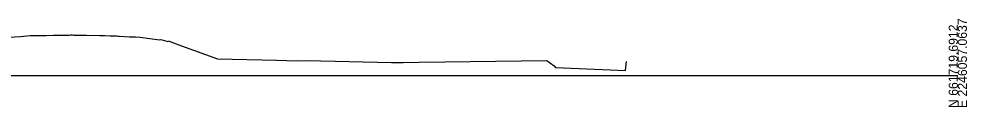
# Model space of a CAD drawing. Extents: x -26 to 603, y -10 to 9526.
# Drawn here: x 311.2 to 602.8, y 990.3 to 1017.3 of the extents above; entities that cross this region are included whole.
import ezdxf

# ---------------------------------------------------------------- set-up
doc = ezdxf.new("R2010")
doc.units = 0
doc.layers.add('Exist Cross Section Cell', color=7, linetype='Continuous')
doc.layers.add('Exist XS Ground Line', color=7, linetype='Continuous')

msp = doc.modelspace()

# ---------------------------------------------------------------- linework, layer by layer
at = {"layer": 'Exist Cross Section Cell'}
msp.add_line((300, 1000), (600, 1000), dxfattribs=at)
at = {"layer": 'Exist XS Ground Line'}
for p, q in [((311.64, 1011.98), (314.69, 1012.19)), ((314.69, 1012.19), (315.53, 1012.27)), ((315.53, 1012.27), (316.19, 1012.24)), ((316.19, 1012.24), (318.76, 1012.26)), ((318.76, 1012.26), (319.58, 1012.27)), ((319.58, 1012.27), (321.78, 1012.3)), ((321.78, 1012.3), (325.08, 1012.34)), ((325.08, 1012.34), (325.81, 1012.36)), ((325.81, 1012.36), (326.64, 1012.39)), ((326.64, 1012.39), (327.09, 1012.4)), ((327.09, 1012.4), (327.64, 1012.4)), ((327.64, 1012.4), (328.05, 1012.37)), ((328.05, 1012.37), (330.09, 1012.33)), ((330.09, 1012.33), (330.57, 1012.32)), ((330.57, 1012.32), (331.84, 1012.29)), ((331.84, 1012.29), (336.06, 1012.22)), ((336.06, 1012.22), (337.65, 1012.2)), ((337.65, 1012.2), (339.29, 1012.18)), ((339.29, 1012.18), (340.08, 1012.15)), ((340.08, 1012.15), (341.25, 1012.12)), ((341.25, 1012.12), (341.66, 1012.01)), ((303.16, 1011.48), (311.64, 1011.98)), ((341.66, 1012.01), (342, 1012)), ((342, 1012), (345.2, 1011.86)), ((345.2, 1011.86), (347.04, 1011.79)), ((347.04, 1011.79), (348.48, 1011.73)), ((348.48, 1011.73), (354.43, 1010.95)), ((354.43, 1010.95), (354.82, 1010.97)), ((354.82, 1010.97), (357.02, 1010.44)), ((357.02, 1010.44), (357.07, 1010.61)), ((357.07, 1010.61), (361.2, 1009.09)), ((361.2, 1009.09), (372.25, 1005.09)), ((372.25, 1005.09), (390.38, 1004.68)), ((390.38, 1004.68), (396.74, 1004.5)), ((396.74, 1004.5), (399.76, 1004.53)), ((399.76, 1004.53), (425.82, 1003.96)), ((425.82, 1003.96), (429.34, 1003.99)), ((429.34, 1003.99), (434.26, 1004.08)), ((434.26, 1004.08), (473.62, 1004.56)), ((473.62, 1004.56), (475.84, 1002.91)), ((497.74, 1001.47), (498.04, 1004.27)), ((475.84, 1002.91), (476.23, 1002.46)), ((476.23, 1002.46), (483.53, 1002.16)), ((483.53, 1002.16), (497.74, 1001.47))]:
    msp.add_line(p, q, dxfattribs=at)

# ---------------------------------------------------------------- texts
at = {"layer": 'Exist Cross Section Cell'}
for s, p in [('N 661719.6912', (600, 990)), ('E 2246057.0637', (602.8, 990))]:
    msp.add_text(s, height=2.8, rotation=90, dxfattribs=at).set_placement(p)

doc.saveas('drawing.dxf')
